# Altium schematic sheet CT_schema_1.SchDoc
size 721 x 682 mm
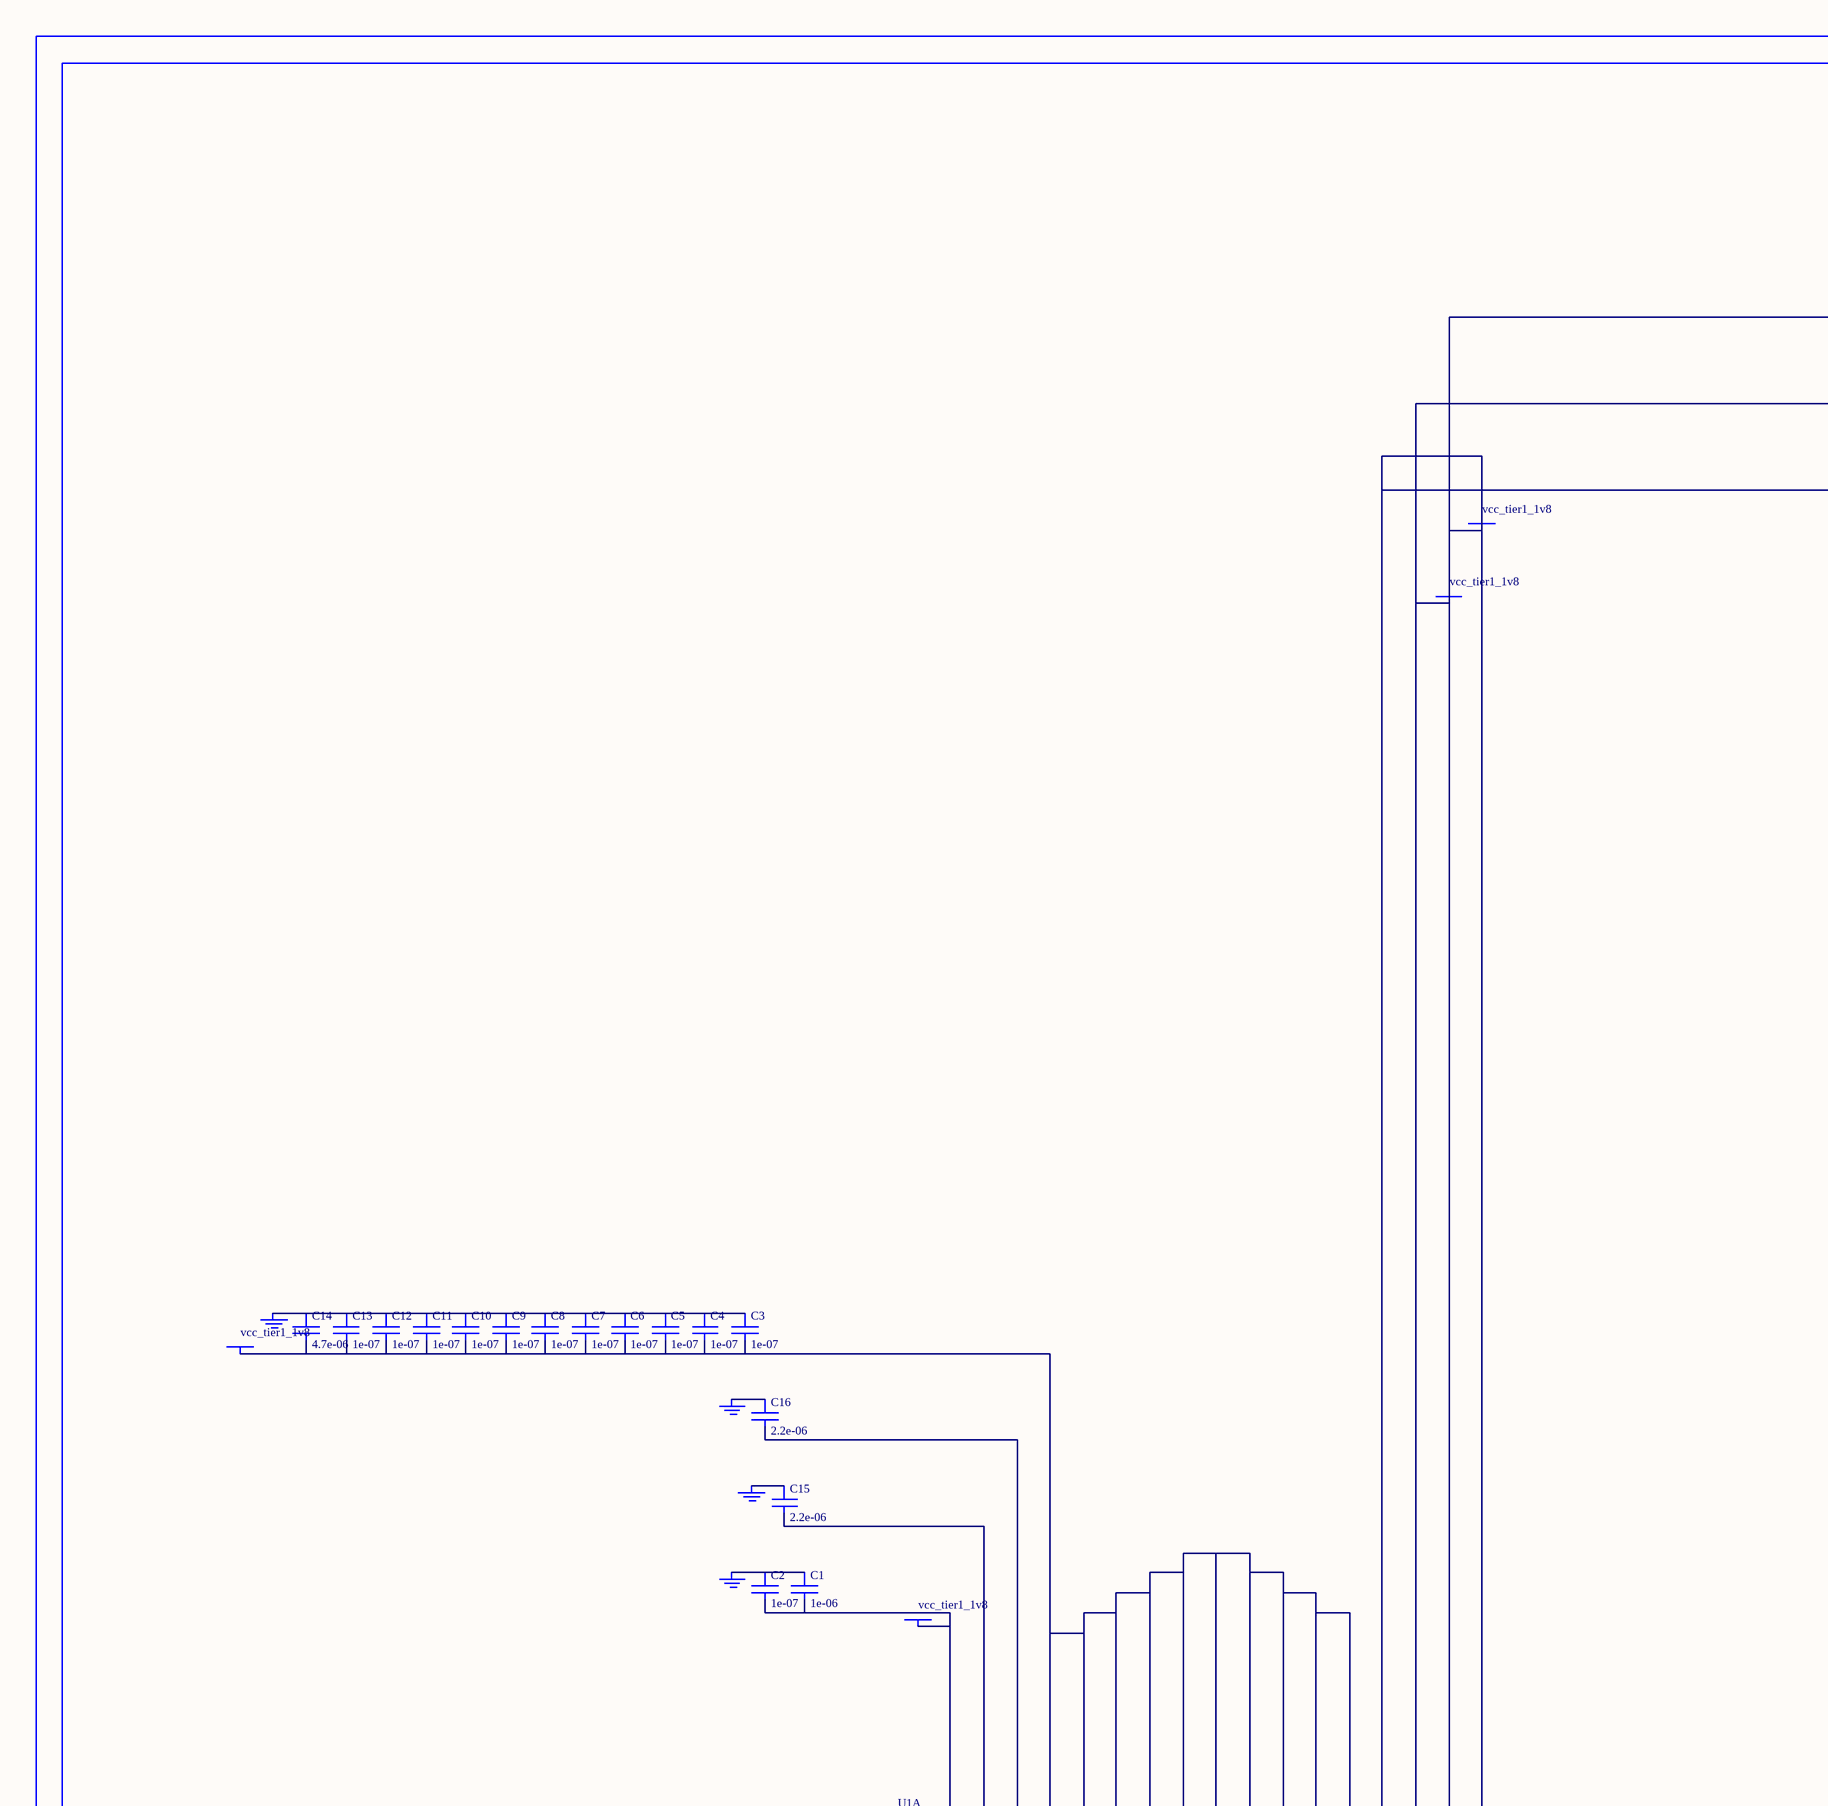
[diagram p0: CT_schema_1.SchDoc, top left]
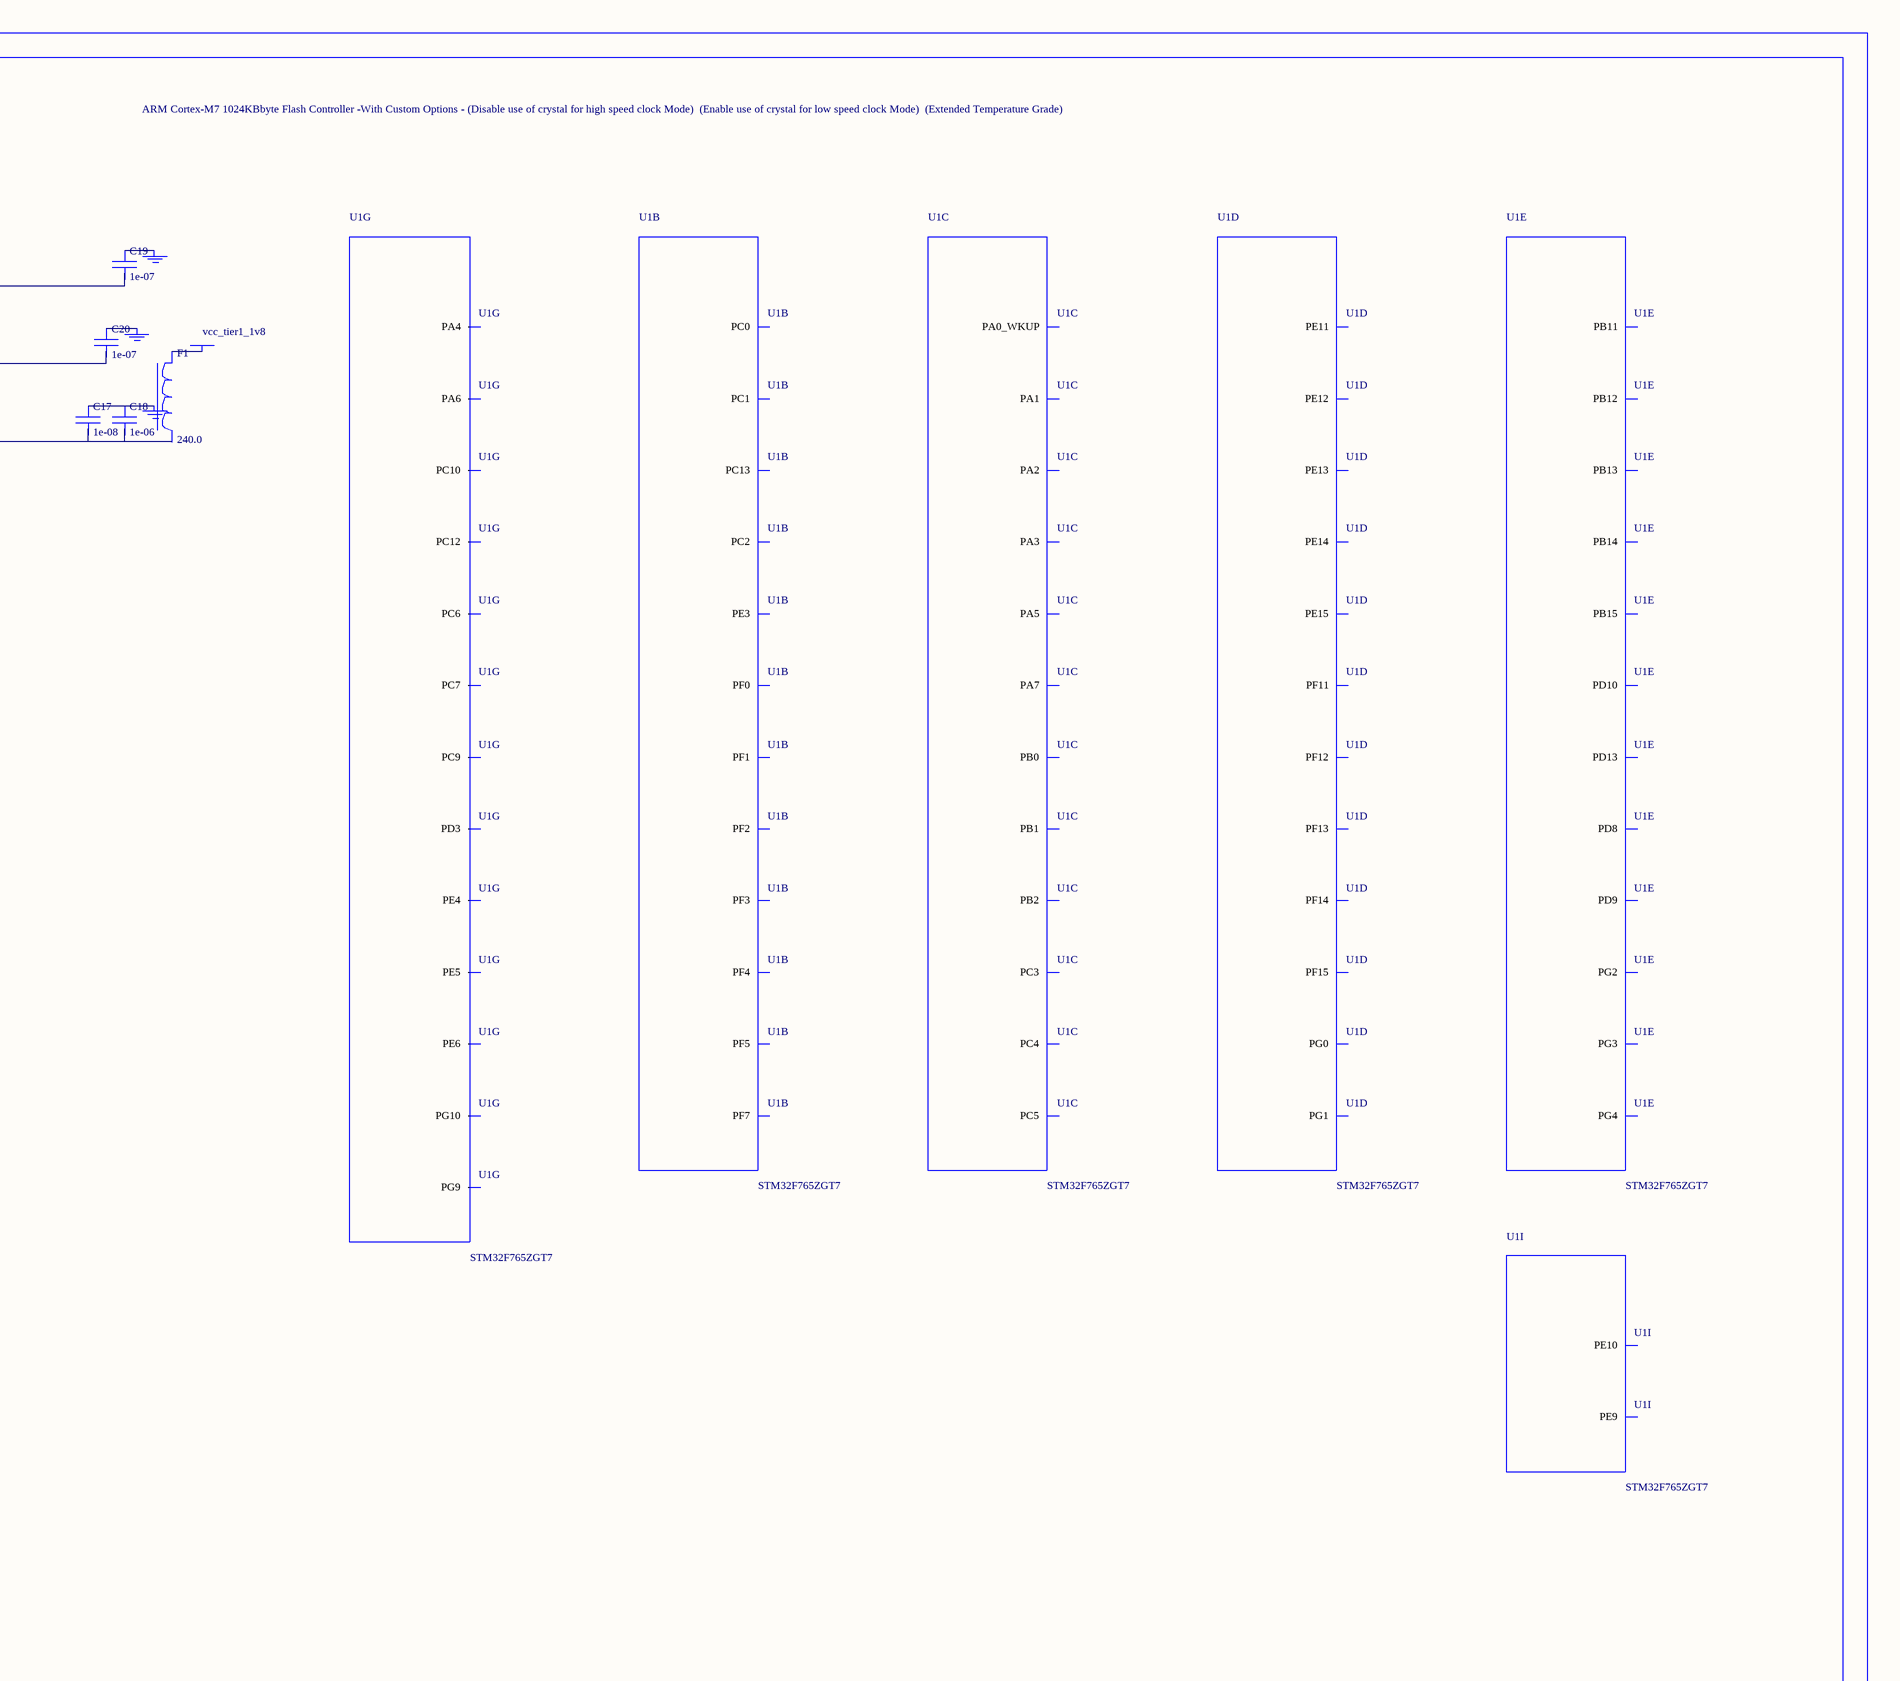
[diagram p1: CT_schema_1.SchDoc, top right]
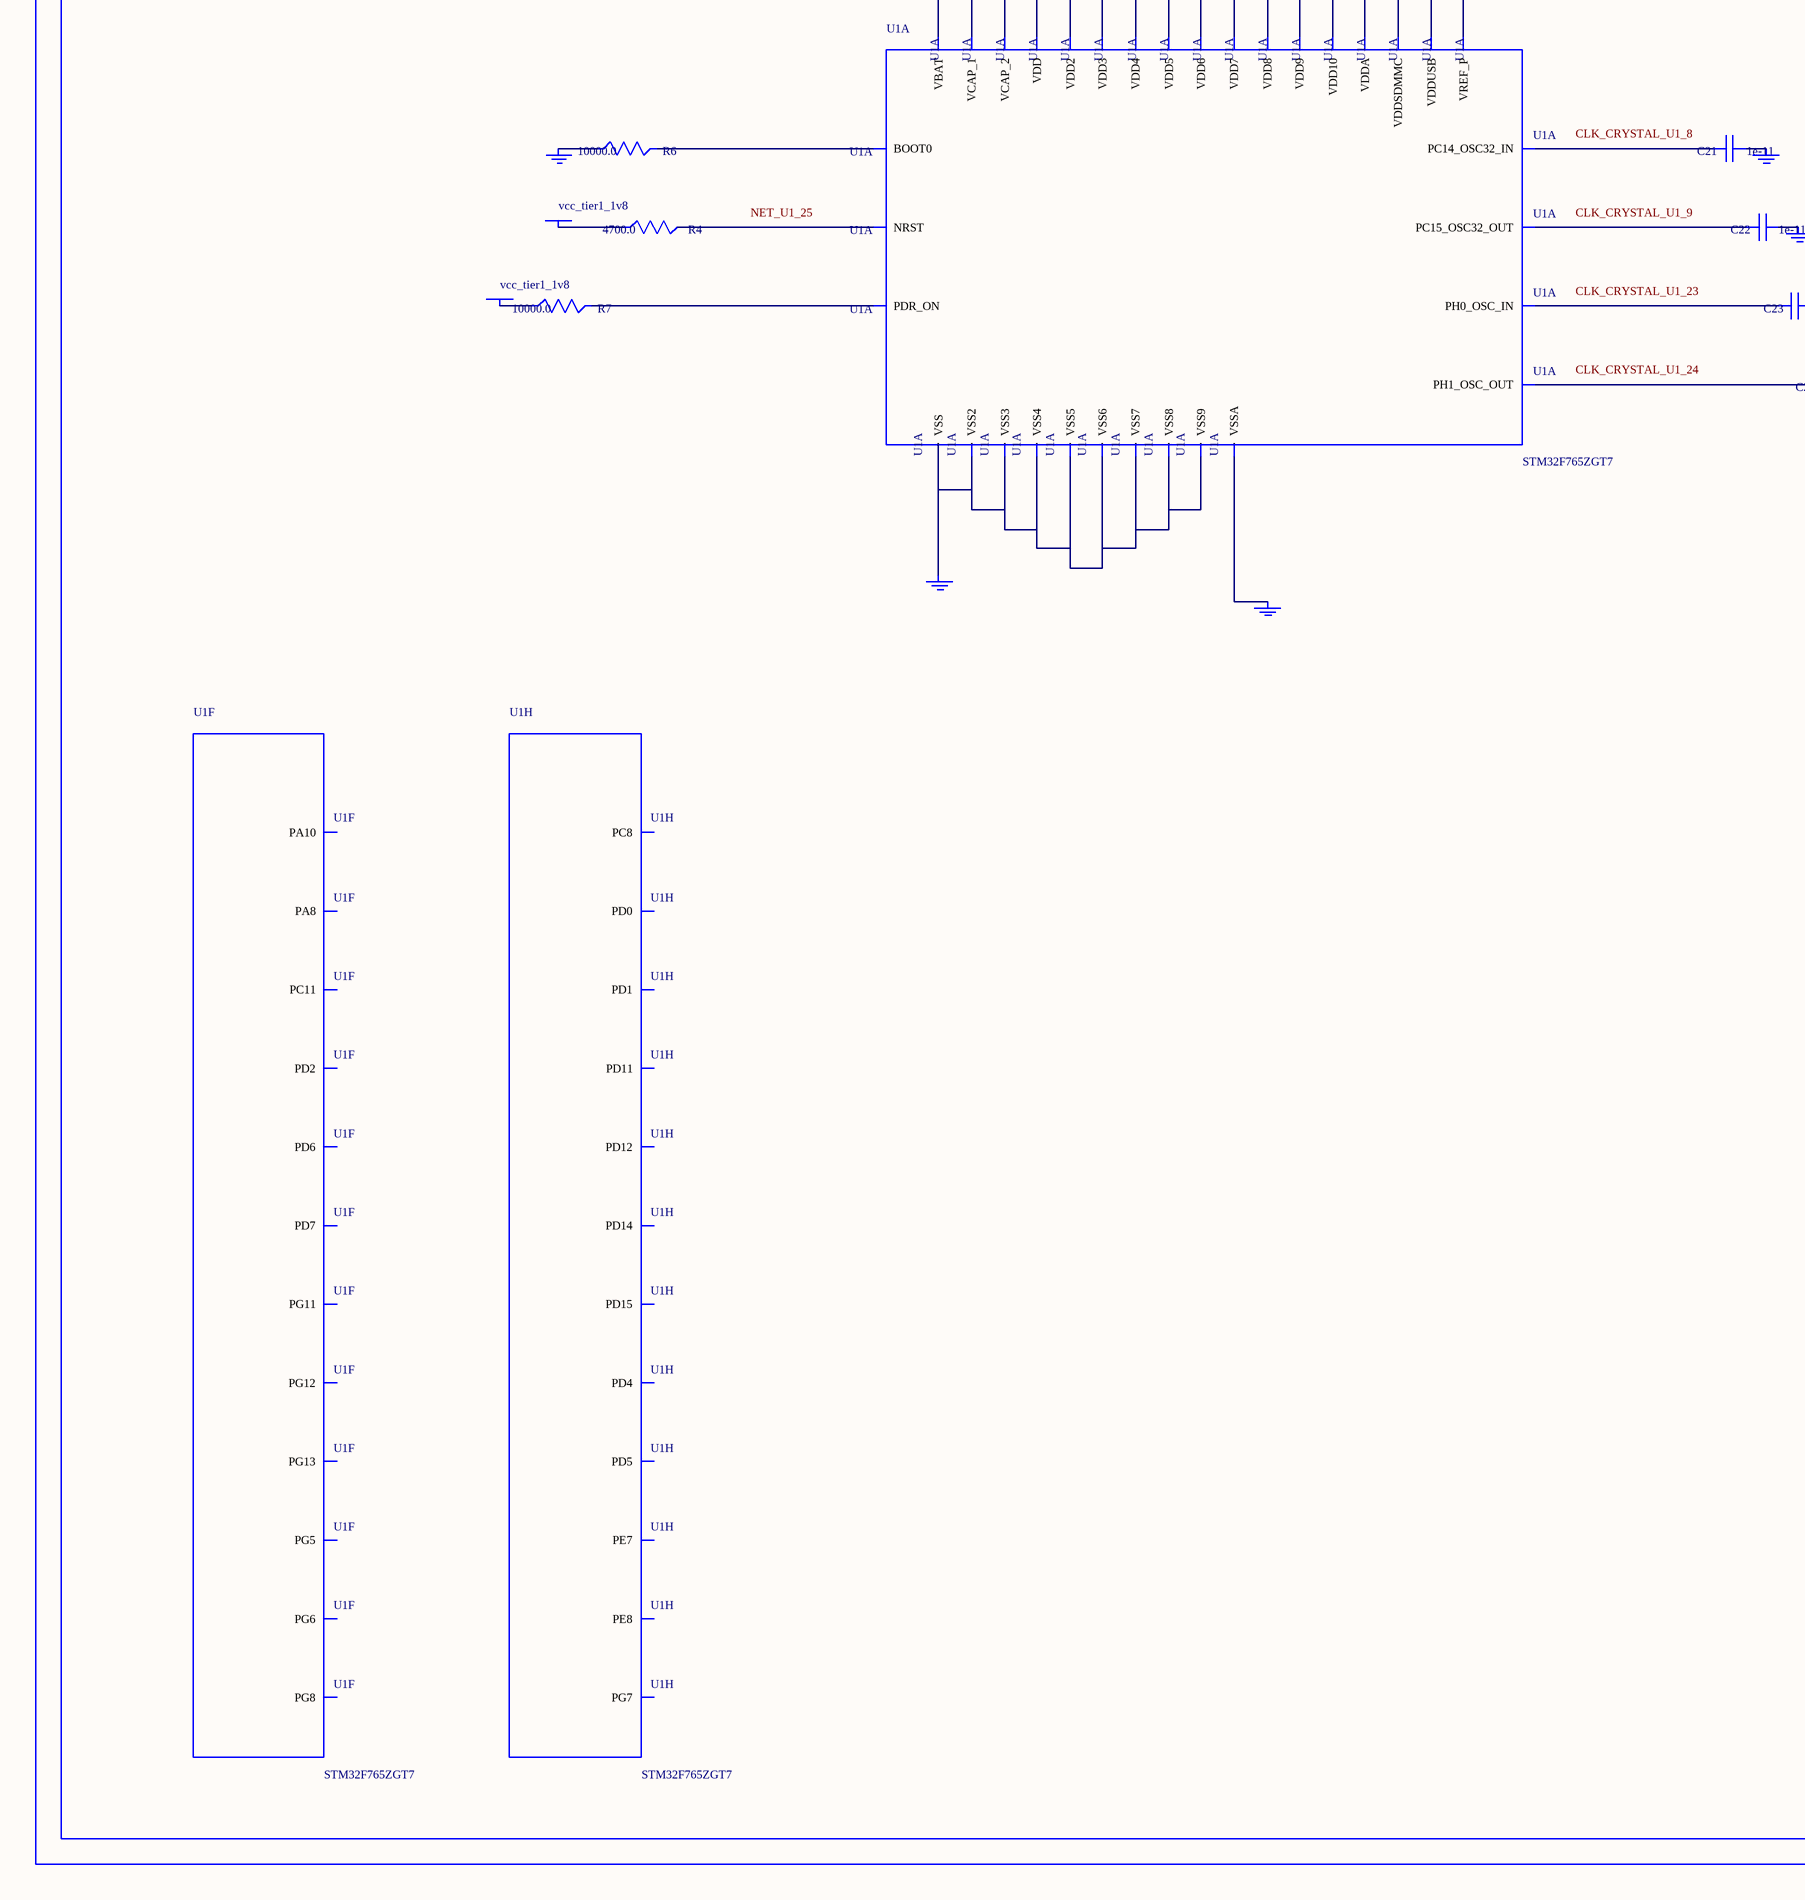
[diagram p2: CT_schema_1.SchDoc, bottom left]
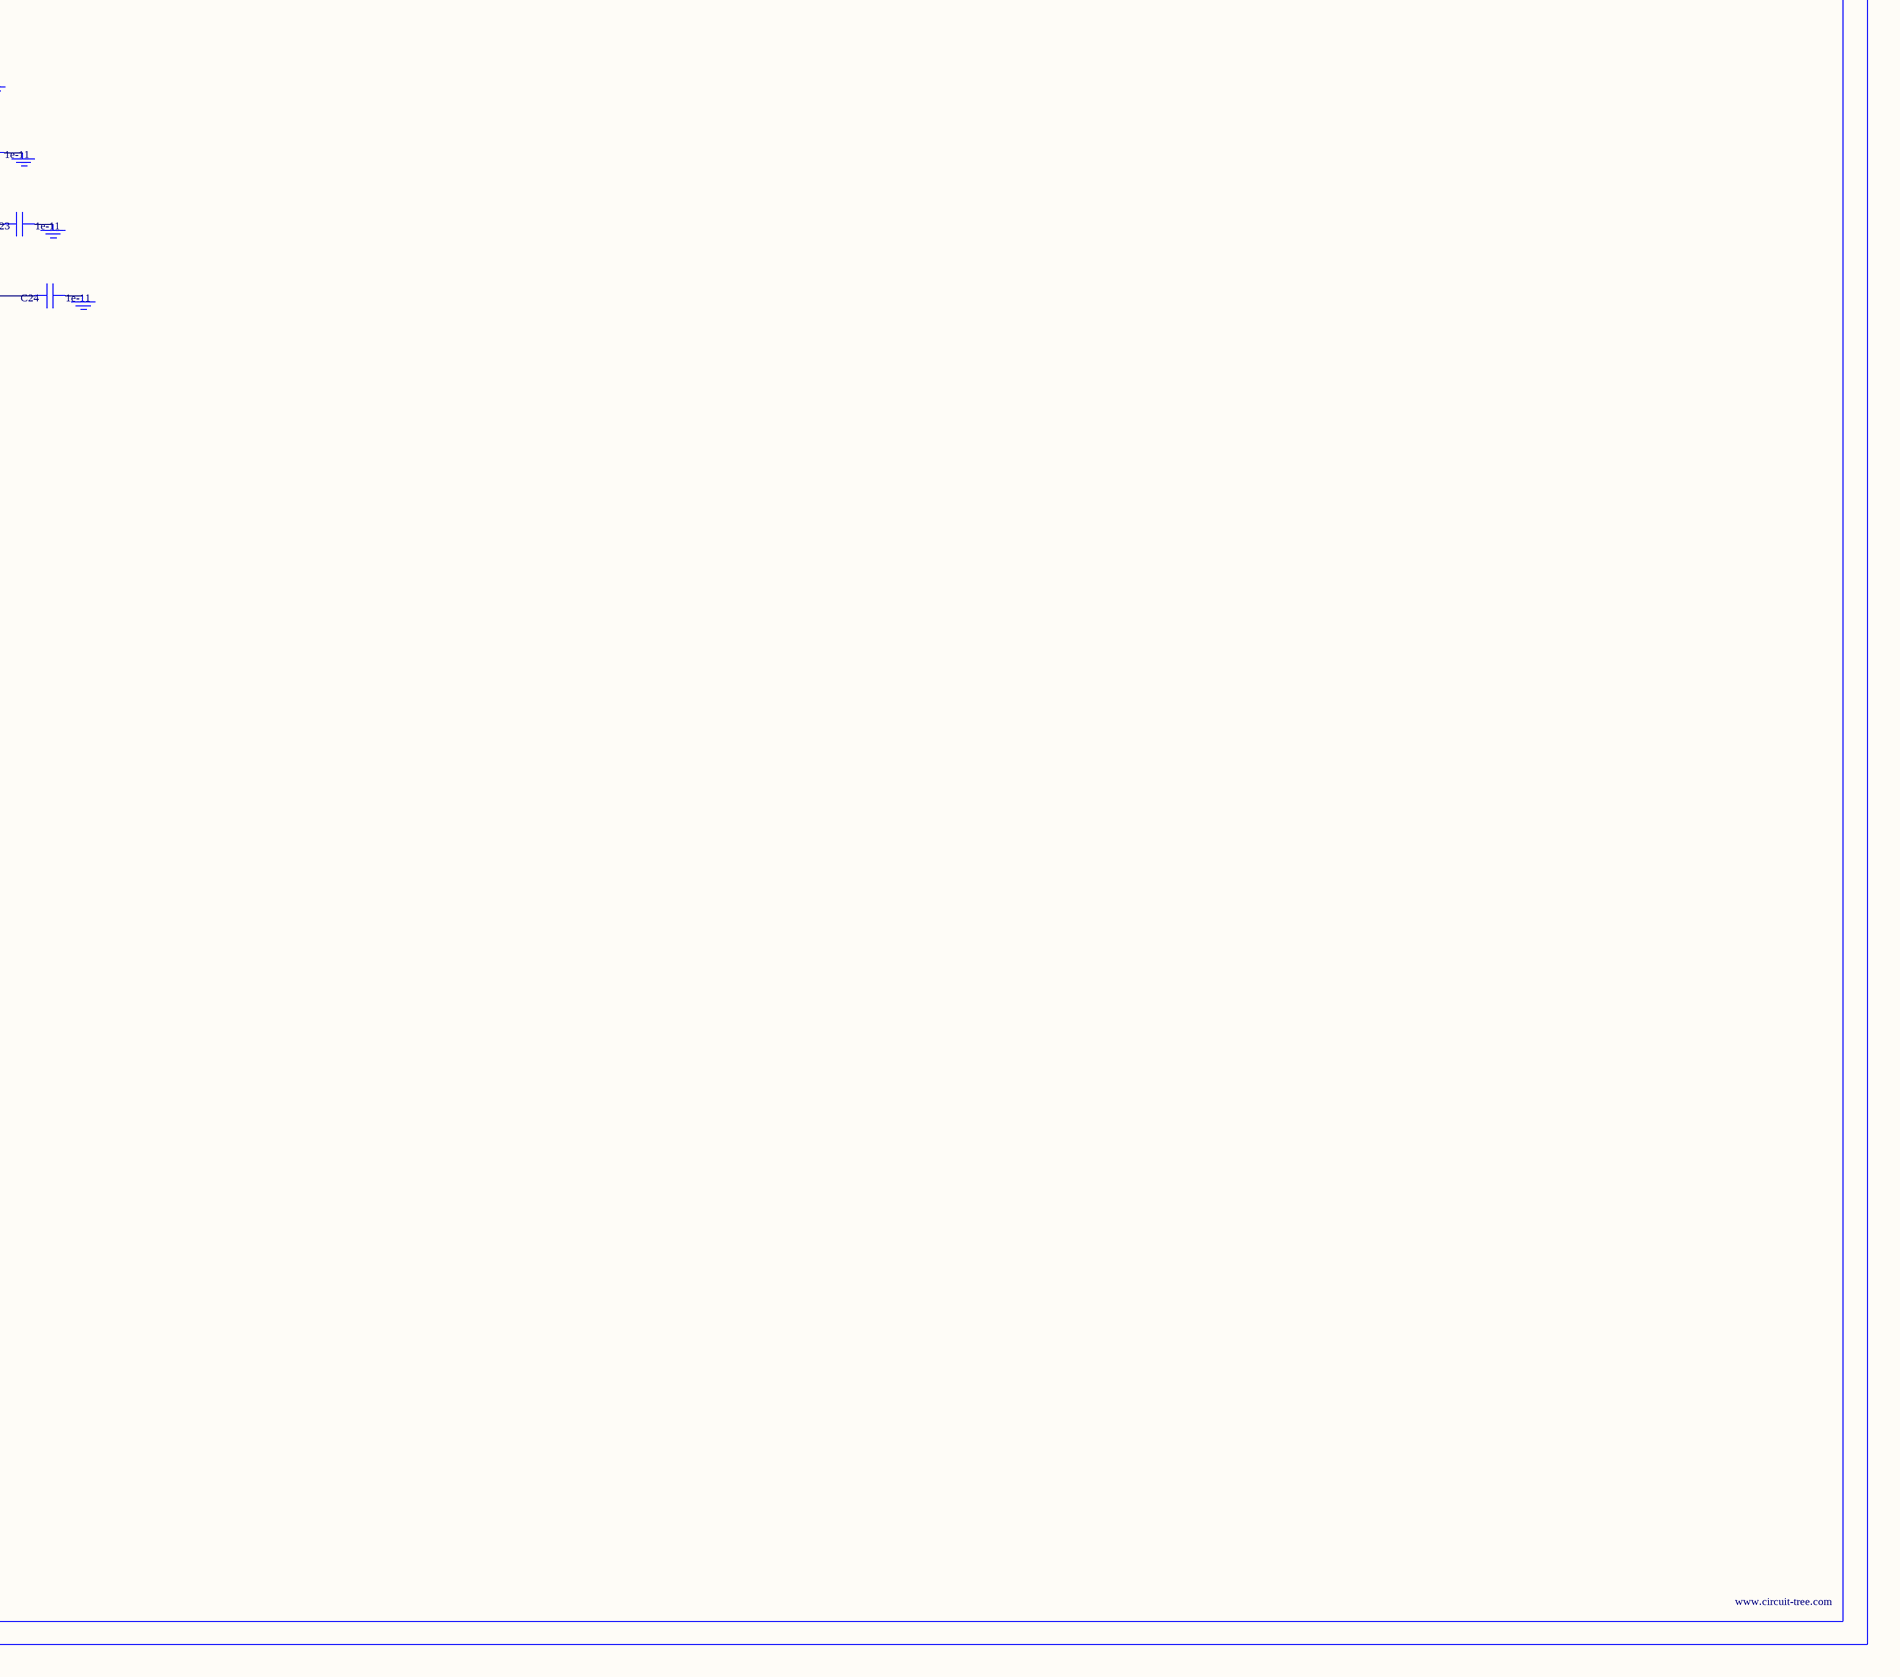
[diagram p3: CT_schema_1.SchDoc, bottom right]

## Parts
BORDER0  (no value)
C1  1e-06  [C0603]
C2  1e-07  [C0603]
C3  1e-07  [C0603]
C4  1e-07  [C0603]
C5  1e-07  [C0603]
C6  1e-07  [C0603]
C7  1e-07  [C0603]
C8  1e-07  [C0603]
C9  1e-07  [C0603]
C10  1e-07  [C0603]
C11  1e-07  [C0603]
C12  1e-07  [C0603]
C13  1e-07  [C0603]
C14  4.7e-06  [C0603]
C15  2.2e-06  [C0603]
C16  2.2e-06  [C0603]
C17  1e-08  [C0603]
C18  1e-06  [C0603]
C19  1e-07  [C0603]
C20  1e-07  [C0603]
C21  1e-11  [C0402]
C22  1e-11  [C0402]
C23  1e-11  [C0402]
C24  1e-11  [C0402]
F1  240.0  [L0603]
GND_INSTANCE_0_0  (no value)
GND_INSTANCE_0_1  (no value)
GND_INSTANCE_0_2  (no value)
GND_INSTANCE_0_3  (no value)
GND_INSTANCE_0_4  (no value)
GND_INSTANCE_0_5  (no value)
GND_INSTANCE_0_6  (no value)
GND_INSTANCE_0_7  (no value)
GND_INSTANCE_0_8  (no value)
GND_INSTANCE_0_9  (no value)
GND_INSTANCE_0_10  (no value)
GND_INSTANCE_0_11  (no value)
GND_INSTANCE_0_12  (no value)
GND_INSTANCE_0_13  (no value)
POWER_INSTANCE_0_0  vcc_tier1_1v8
POWER_INSTANCE_0_1  vcc_tier1_1v8
POWER_INSTANCE_0_2  vcc_tier1_1v8
POWER_INSTANCE_0_3  vcc_tier1_1v8
POWER_INSTANCE_0_4  vcc_tier1_1v8
POWER_INSTANCE_0_5  vcc_tier1_1v8
POWER_INSTANCE_0_6  vcc_tier1_1v8
R4  4700.0  [R0603]
R6  10000.0  [R0603]
R7  10000.0  [R0603]
U1  STM32F765ZGT7  [LQFP144]  (parts A,B,C,D,E,F,G,H,I of 11)

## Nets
NetC1_1: C1.1 C2.1 GND_INSTANCE_0_0.0(GND)
NetC1_2: C1.2 C2.2 POWER_INSTANCE_0_0.0(PWR) U1.6(VBAT)
NetC3_1: C3.1 C4.1 C5.1 C6.1 C7.1 C8.1 C9.1 C10.1 C11.1 C12.1 C13.1 C14.1 GND_INSTANCE_0_3.0(GND)
NetC3_2: C3.2 C4.2 C5.2 C6.2 C7.2 C8.2 C9.2 C10.2 C11.2 C12.2 C13.2 C14.2 POWER_INSTANCE_0_1.0(PWR) U1.17(VDD) U1.30(VDD2) U1.39(VDD3) U1.52(VDD4) U1.62(VDD5) U1.72(VDD6) U1.84(VDD7) U1.108(VDD8) U1.131(VDD9) U1.144(VDD10)
NetC15_1: C15.1 GND_INSTANCE_0_8.0(GND)
NetC15_2: C15.2 U1.71(VCAP_1)
NetC16_1: C16.1 GND_INSTANCE_0_10.0(GND)
NetC16_2: C16.2 U1.106(VCAP_2)
NetC17_1: C17.1 C18.1 GND_INSTANCE_0_7.0(GND)
NetC17_2: C17.2 C18.2 C19.2 C20.2 POWER_INSTANCE_0_3.0(PWR) POWER_INSTANCE_0_4.0(PWR) U1.32(VREF_P) U1.33(VDDA) U1.95(VDDUSB) U1.121(VDDSDMMC)
NetC19_1: C19.1 GND_INSTANCE_0_9.0(GND)
NetC20_1: C20.1 GND_INSTANCE_0_11.0(GND)
NetC21_1: C21.1 GND_INSTANCE_0_1.0(GND)
NetC21_2: C21.2 U1.8(PC14_OSC32_IN)
NetC22_1: C22.1 GND_INSTANCE_0_2.0(GND)
NetC22_2: C22.2 U1.9(PC15_OSC32_OUT)
NetC23_1: C23.1 GND_INSTANCE_0_4.0(GND)
NetC23_2: C23.2 U1.23(PH0_OSC_IN)
NetC24_1: C24.1 GND_INSTANCE_0_5.0(GND)
NetC24_2: C24.2 U1.24(PH1_OSC_OUT)
NetF1_1: F1.1 POWER_INSTANCE_0_2.0(PWR)
NetGND_INSTANCE_0_6_0: GND_INSTANCE_0_6.0(GND) U1.31(VSSA)
NetGND_INSTANCE_0_12_0: GND_INSTANCE_0_12.0(GND) R6.1
NetGND_INSTANCE_0_13_0: GND_INSTANCE_0_13.0(GND) U1.16(VSS) U1.38(VSS2) U1.51(VSS3) U1.61(VSS4) U1.83(VSS5) U1.94(VSS6) U1.107(VSS7) U1.120(VSS8) U1.130(VSS9)
NetPOWER_INSTANCE_0_5_0: POWER_INSTANCE_0_5.0(PWR) R7.1
NetPOWER_INSTANCE_0_6_0: POWER_INSTANCE_0_6.0(PWR) R4.1
NetR4_2: R4.2 U1.25(NRST)
NetR6_2: R6.2 U1.138(BOOT0)
NetR7_2: R7.2 U1.143(PDR_ON)

Not connected (* = marked no-connect by the designer): F1 2; U1 2(PE3) 3(PE4) 4(PE5) 5(PE6) 7(PC13) 10(PF0) 11(PF1) 12(PF2) 13(PF3) 14(PF4) 15(PF5) 19(PF7) 26(PC0) 27(PC1) 28(PC2) 29(PC3) 34(PA0_WKUP) 35(PA1) 36(PA2) 37(PA3) 40(PA4) 41(PA5) 42(PA6) 43(PA7) 44(PC4) 45(PC5) 46(PB0) 47(PB1) 48(PB2) 49(PF11) 50(PF12) 53(PF13) 54(PF14) 55(PF15) 56(PG0) 57(PG1) 58(PE7) 59(PE8) 60(PE9) 63(PE10) 64(PE11) 65(PE12) 66(PE13) 67(PE14) 68(PE15) 70(PB11) 73(PB12) 74(PB13) 75(PB14) 76(PB15) 77(PD8) 78(PD9) 79(PD10) 80(PD11) 81(PD12) 82(PD13) 85(PD14) 86(PD15) 87(PG2) 88(PG3) 89(PG4) 90(PG5) 91(PG6) 92(PG7) 93(PG8) 96(PC6) 97(PC7) 98(PC8) 99(PC9) 100(PA8) 102(PA10) 111(PC10) 112(PC11) 113(PC12) 114(PD0) 115(PD1) 116(PD2) 117(PD3) 118(PD4) 119(PD5) 122(PD6) 123(PD7) 124(PG9) 125(PG10) 126(PG11) 127(PG12) 128(PG13)

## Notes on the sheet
- Labels drawn without touching a wire or pin: CLK_CRYSTAL_U1_8, CLK_CRYSTAL_U1_9, CLK_CRYSTAL_U1_23, CLK_CRYSTAL_U1_24, NET_U1_25

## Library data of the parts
BORDER0 = BORDER_PAGE0
C1 C18 = C0603C105K3RACTU
C2-C13 C19 C20 = 06035C104K4Z2A
C14 = GRM188R6YA475KE15D
C15 C16 = C0603C225K8RACTU
C17 = 06035C103K4Z2A
C21-C24 = C0402C100K3GACTU
F1 = Z0603C241ASMST
GND_INSTANCE_0_0-GND_INSTANCE_0_13 = GND
POWER_INSTANCE_0_0-POWER_INSTANCE_0_6 = PWR
R4 = RC0603JR-074K7L
R6 R7 = RC0603JR-0710KL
